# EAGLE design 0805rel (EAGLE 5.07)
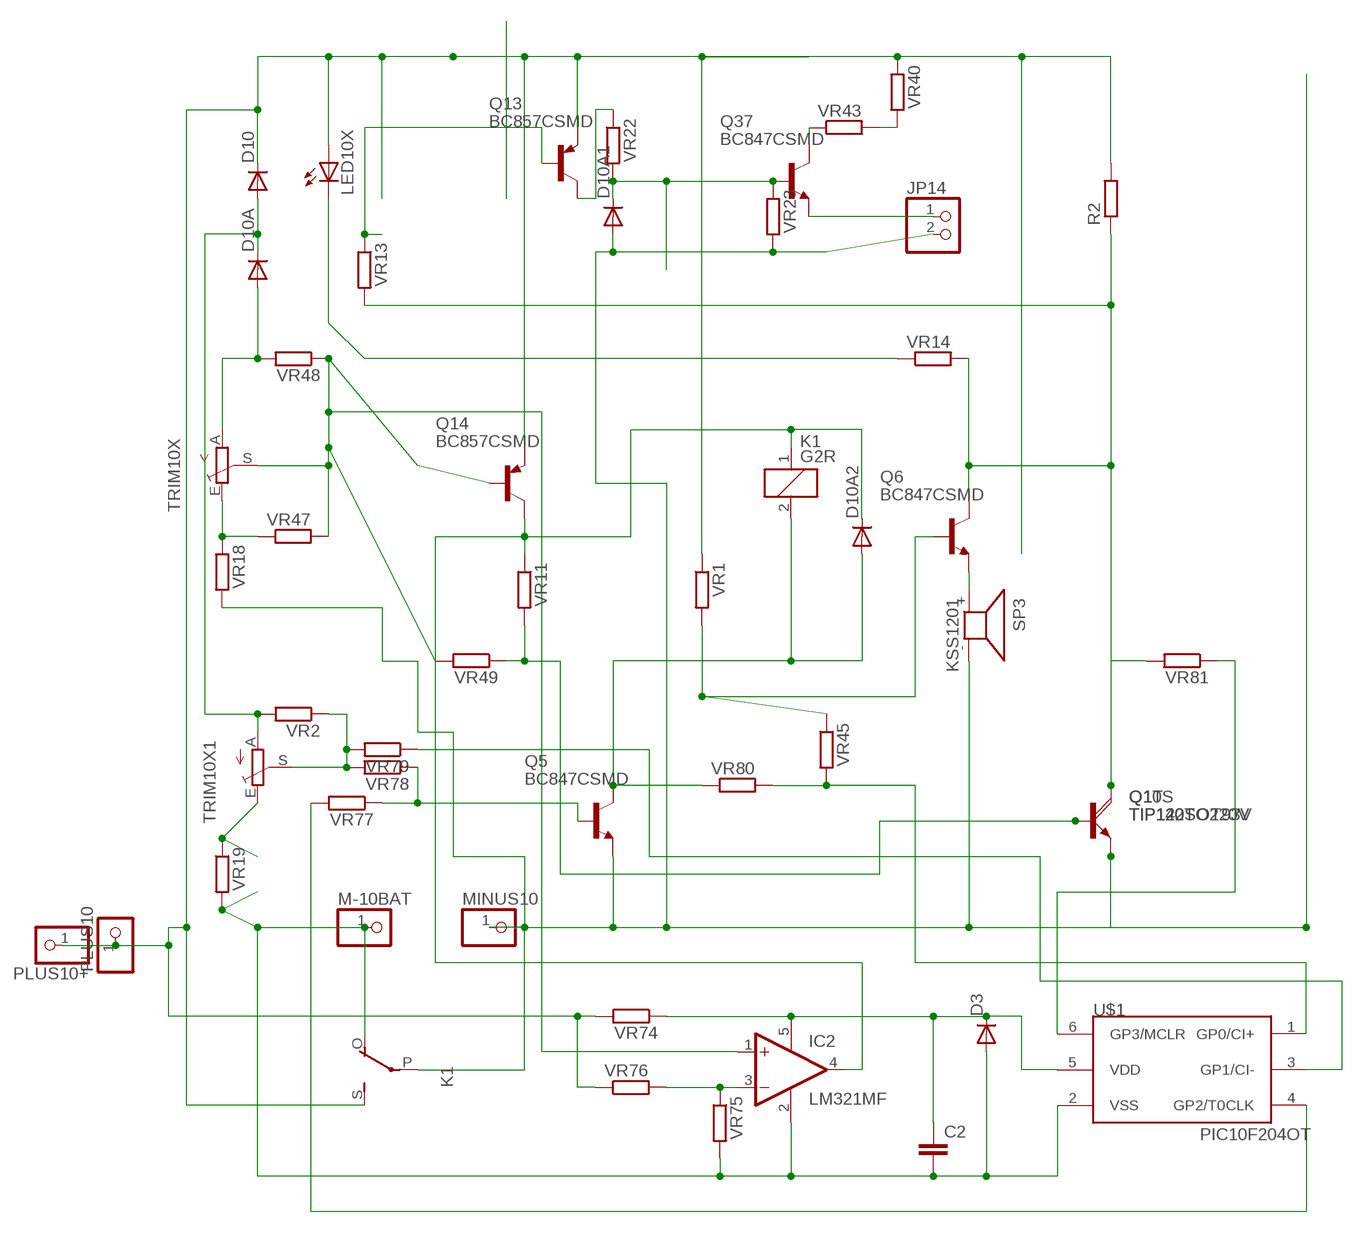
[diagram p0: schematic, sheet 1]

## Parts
C2  C-EUC0805  [C0805]
D3  DIODE-MINIMELF  [MINIMELF]
D10  DIODE-MINIMELF  [MINIMELF]
D10A  DIODE-MINIMELF  [MINIMELF]
D10A1  DIODE-MINIMELF  [MINIMELF]
D10A2  DIODE-MINIMELF  [MINIMELF]
IC2  LM321MF  [SOT23-5]
JP14  PINHD-1X2STR  [1X02]
K1  G2R  [G2R]
LED10X  LEDCHIPLED_1206  [CHIPLED_1206]
M-10BAT  PINHD-1X11X0.4  [1X01]
MINUS10  PINHD-1X14.5MM  [1X4MM5]
PLUS10  PINHD-1X14.5MM  [1X4MM5]
PLUS10+  PINHD-1X11X0.4  [1X01]
Q1  TIP142SOT93V  [SOT93V]
Q1T  TIP120TO220V  [TO220AV]
Q5  BC847CSMD  [SOT23]
Q6  BC847CSMD  [SOT23]
Q10S  TIP120  TIP120DPAK  [D-PAK_TO252AA]
Q13  BC857CSMD  [SOT23-BEC]
Q14  BC857CSMD  [SOT23-BEC]
Q37  BC847CSMD  [SOT23]
R2  R-EU_CERAM85  [CERAM85]
SP3  KSS1201  [KSS1201]
TRIM10X  TRIM_EU-S64W  [S64W]
TRIM10X1  TRIM_EU-S64W  [S64W]
U$1  PIC10F204OT  [SOT23-6]
VR1  R-EU_R0805  [R0805]
VR2  R-EU_R0805  [R0805]
VR11  R-EU_R0805  [R0805]
VR13  R-EU_R0805  [R0805]
VR14  R-EU_R0805  [R0805]
VR18  R-EU_R1206  [R1206]
VR19  R-EU_R1206  [R1206]
VR22  R-EU_R0805  [R0805]
VR23  R-EU_R0805  [R0805]
VR40  R-EU_R1206  [R1206]
VR43  R-EU_R1206  [R1206]
VR45  R-EU_R0805  [R0805]
VR47  R-EU_R0805  [R0805]
VR48  R-EU_R0805  [R0805]
VR49  R-EU_R0805  [R0805]
VR74  R-EU_R0805  [R0805]
VR75  R-EU_R0603  [R0603]
VR76  R-EU_R0805  [R0805]
VR77  R-EU_R0805  [R0805]
VR78  R-EU_R0805  [R0805]
VR79  R-EU_R0805  [R0805]
VR80  R-EU_R0805  [R0805]
VR81  R-EU_R0805  [R0805]

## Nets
B: IC2.1(+IN) Q14.B TRIM10X.S VR47.2 VR48.1 VR49.2
B2: U$1.4(GP2/T0CLK) VR77.2
E10: D10A1.A JP14.2 K1.P(2:P) MINUS10.1 Q1.E Q1T.E Q5.2(E) Q10S.3(E) SP3.- VR18.2 VR23.2
GP3: Q6.2(E) SP3.+
N$11: LED10X.C VR14.1
N$14: D10A.A TRIM10X.A VR48.2
N$15: D10A2.C IC2.4(OUT) K1.1 Q14.C VR11.1
N$17: D10.A D10A.C TRIM10X1.A VR2.2
N$22: TRIM10X1.S VR2.1 VR78.2 VR79.2
N$23: Q13.B VR13.1
N$24: TRIM10X1.E VR19.1
N$25: Q1.B Q1T.B Q10S.1(B) VR11.2 VR49.1
N$128: TRIM10X.E VR18.1 VR47.1
N$136: JP14.1 Q37.2(E)
N$138: U$1.1(GP0/CI+) VR45.2 VR80.2
N$146: Q6.1(B) VR1.2 VR45.1
N$149: IC2.3(-IN) VR75.1 VR76.2
N$159: Q13.C VR22.1
N$163: VR40.2 VR43.2
N$164: Q37.3(C) VR43.1
N$165: U$1.3(GP1/CI-) VR79.1
N$168: Q5.1(B) VR77.1 VR78.1
N$169: D10A2.A K1.2 Q5.3(C) VR80.1
N$170: U$1.6(GP3/MCLR) VR81.1
N$179: D10A1.C Q37.1(B) VR22.2 VR23.1
PLUS11: D10.C K1.S(2:S) LED10X.A PLUS10+.1 PLUS10.1 Q13.E Q14.E R2.2 VR1.1 VR40.1 VR74.2 VR76.1
Q10C: Q1.C Q1T.C Q6.3(C) Q10S.4(C) R2.1 VR13.2 VR14.2 VR81.2
V3: C2.1 D3.C IC2.5(V+) U$1.5(VDD) VR74.1
VSS: C2.2 D3.A IC2.2(V-) K1.O(2:O) M-10BAT.1 U$1.2(VSS) VR19.2 VR75.2

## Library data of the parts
C2 = rcl:C-EU: CAPACITOR, European symbol
D3 D10 D10A D10A1 D10A2 = diode:DIODE-: DIODE
IC2 = linear:LM321?*: Low Power Single Op Amp Source: http://cache.national.com/ds/LM/LM321.pdf
JP14 = pinhead:PINHD-1X2: PIN HEADER
K1 = relay:G2R: RELAY 1 x switch, Omron
LED10X = led:LED: LED
M-10BAT MINUS10 PLUS10 PLUS10+ = pinhead:PINHD-1X1: PIN HEADER
Q1 = transistor-power:TIP142: NPN DARLINGTON TRANSISTOR
Q1T Q10S = transistor-power:TIP120: NPN DARLINGTON TRANSISTOR
Q5 Q6 Q37 = transistor-npn:BC847*: NPN Transistor
Q13 Q14 = transistor-pnp:BC857*: PNP Transistror
R2 = rcl:R-EU_: RESISTOR, European symbol
SP3 = buzzer:KSS1201: SPEAKER
TRIM10X TRIM10X1 = pot:TRIM_EU-: POTENTIOMETER
U$1 = microchip-3:PIC10F2*: uPC nW 0,25/0,5k Program Flash memory Comparator
VR1 VR2 VR11 VR13 VR14 VR18 VR19 VR22 VR23 VR40 VR43 VR45 VR47-VR49 VR74-VR81 = rcl-2:R-EU_: RESISTOR, European symbol

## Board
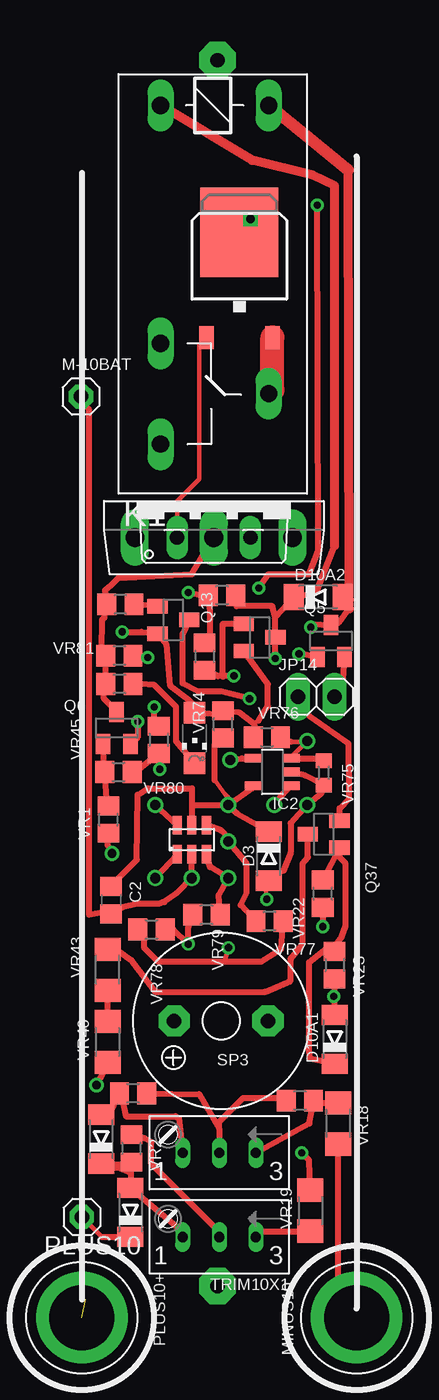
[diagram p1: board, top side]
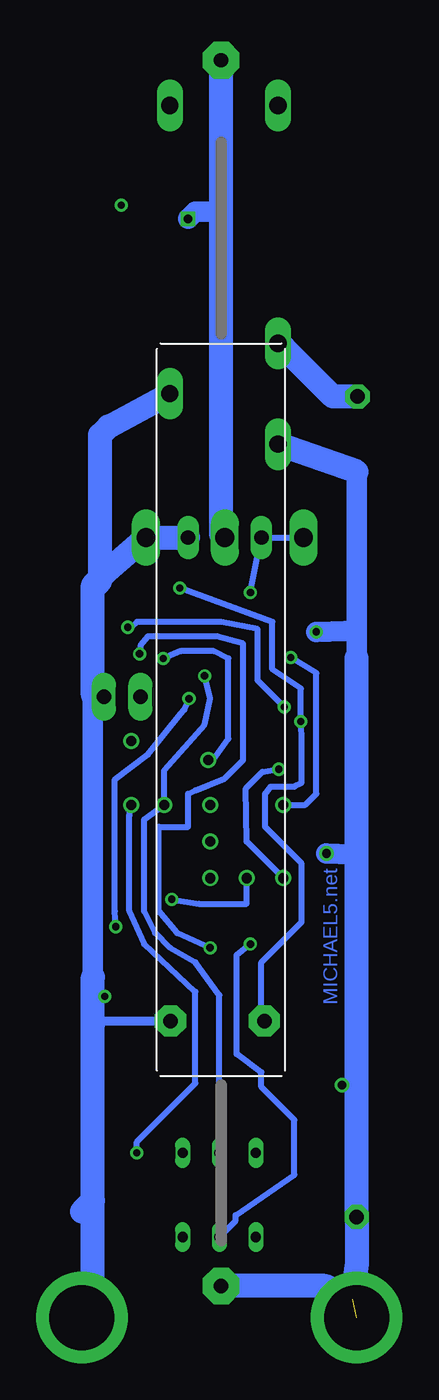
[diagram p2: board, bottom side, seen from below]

No outline drawn. Coordinates in mm, seen from the top.
Copper layers (1*16): Top 0.035mm / dielectric 1.5mm / Bottom 0.035mm
Design rules "default *": minimum track width 8mil, minimum drill 24mil, track to track 8mil, track to pad 8mil, pad to pad 8mil, via to via 8mil, smd to smd 8mil, copper to edge 40mil, drill to drill 8mil, minimum pad ring 1mil, minimum via ring 8mil, stop-mask expansion 4mil, vias tented up to drill 0mil, thermal gap 10mil

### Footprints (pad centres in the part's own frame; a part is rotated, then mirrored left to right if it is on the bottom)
C0805 = smd 1.3 x 1.5: 1 -0.95,0; 2 0.95,0
MINIMELF = smd 1.4 x 1.8: A 1.7,0; C -1.7,0
SOT23-5 = smd 0.6 x 1.2: 1 -0.95,-1.306; 2 0,-1.306; 3 0.95,-1.306; 4 0.95,1.306; 5 -0.95,1.306
1X02 = drill 1.016 pad 1.676 long: 1 -1.27,0; 2 1.27,0
G2R = drill 1.2 pad 1.778 long: 1 -2.54,-3.683; 2 -2.54,3.81; O 13.97,-3.683; P 17.45,3.81; S 20.955,-3.683
CHIPLED_1206 = smd 1.5 x 1.5: A 0,-1.75; C 0,1.75
1X01 = drill 1 pad 1.676 octagon: 1 0,0
1X4MM5 = drill 4.5 pad 6.35 round: 1 0,0
SOT93V = drill 1.3 pad 1.676 long: B -5.461,-2.54; C 0,-2.54; E 5.461,-2.54
TO220AV = drill 1 pad 1.27 long: B -2.54,-2.54; C 0,-2.54; E 2.54,-2.54
SOT23 = smd 1 x 1.4: 1 -0.95,-1.1; 2 0.95,-1.1; 3 0,1.1
D-PAK_TO252AA = smd 1 x 1.6: 1 -2.28,-4.8; 3 2.28,-4.8 | smd 5.4 x 6.2: 4 0,2.5
SOT23-BEC = smd 1 x 1.4: B -0.95,-1.1; C 0,1.1; E 0.95,-1.1
CERAM85 = drill 1 pad 2.54 octagon: 1 -42.5,0; 2 42.5,0
KSS1201 = drill 1 pad 2.159 octagon: + 3.251,0; - -3.251,0
S64W = drill 0.7 long: A 2.54,1.27; E -2.54,1.27; S 0,1.27
SOT23-6 = smd 0.635 x 1.27: 1 -1.016,-1.016; 2 0,-1.016; 3 1.016,-1.016; 4 1.016,1.016; 5 0,1.016; 6 -1.016,1.016
R0805 = smd 1.3 x 1.5: 1 -0.95,0; 2 0.95,0
R1206 = smd 1.6 x 1.803: 1 -1.422,0; 2 1.422,0
R0603 = smd 1 x 1.1: 1 -0.85,0; 2 0.85,0

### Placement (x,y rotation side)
C2  73.15,37.85 270 top
D3  84.07,40.89 270 top
D10  74.49,16.19 90 top
D10A  72.45,21.27 90 top
D10A1  88.65,28.19 90 top
D10A2  87.5,58.86 0 top
IC2  84.33,46.74 90 top
JP14  87.38,51.94 0 top
K1  80.26,90.42 270 top
LED10X  78.93,49.09 180 top
M-10BAT  71.06,72.77 0 top
MINUS10  90.17,8.89 0 top
PLUS10  71.12,8.89 0 top
PLUS10+  71.12,15.88 0 top
Q1  80.26,65.53 0 top
Q1T  80.26,65.53 0 top
Q5  88.39,55.82 0 top
Q6  73.53,49.78 0 top
Q10S  82.04,81.66 0 top
Q13  77.47,57.28 270 top
Q14  83.44,56.07 270 top
Q37  87.88,42.42 90 top
R2  80.52,53.59 270 bottom
SP3  80.77,29.46 180 top
TRIM10X  80.64,21.59 180 top
TRIM10X1  80.64,15.75 180 top
U$1  78.74,42.04 0 top
VR1  72.96,43.43 90 top
VR2  74.55,20.64 270 top
VR11  80.84,58.99 180 top
VR13  73.79,58.36 180 top
VR14  73.72,52.83 180 top
VR18  88.9,22.35 270 top
VR19  86.97,16.32 90 top
VR22  87.82,38.29 90 top
VR23  88.65,33.34 270 top
VR40  72.9,28 90 top
VR43  72.9,33.02 270 top
VR45  73.66,46.74 0 top
VR47  86.23,23.94 180 top
VR48  74.68,24.45 180 top
VR49  79.63,54.74 270 top
VR74  80.9,50.04 90 top
VR75  87.88,46.67 270 top
VR76  83.95,49.15 0 top
VR77  84.14,36.39 180 top
VR78  75.95,35.81 0 top
VR79  79.76,36.83 180 top
VR80  76.45,48.96 270 top
VR81  73.72,54.8 180 top

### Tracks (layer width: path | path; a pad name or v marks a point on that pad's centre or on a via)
B  (via drill 0.5, 0.7)
  Top 0.406: 80.64,21.97 80.64,22.48 82.3,24.13 85.19,24.13 VR47.2 | 80.64,21.97 TRIM10X.S | 80.64,21.97 79.25,24.38 VR48.1 | v81.66,53.4 81.47,53.38 | v84.45,44.45 85.09,45.24 IC2.1 | VR49.2 80.54,53.38 v81.66,53.4 | Q14.B 82.42,57.02 80.9,57.02 80.9,53.34 v81.66,53.4
  Bottom 0.406: TRIM10X.S 80.64,31.24 82.3,33.53 84.07,34.54 85.09,35.56 85.85,37.08 85.85,43.43 v84.45,44.45 84.45,46.86 81.66,50.04 81.28,51.82 v81.66,53.4
B2  (via drill 0.7)
  Top 0.406: VR77.2 82.13,37.5 82.55,38.35 82.55,40.39 v81.28,41.91 81.28,42.16 80.77,42.67 U$1.4
  Bottom 0.406: v81.28,41.91 81.28,42.16
E10  (via drill 0.5)
  Top 0.406: VR18.2 88.9,10.92 MINUS10.1 | VR23.2 88.71,32.07 v88.58,31.18 D10A1.A | Q5.2 89.22,52.64 JP14.2
  Top 1.676: K1.P 84.32,73.22 Q10S.3
  Bottom 0.406: MINUS10.1 89.41,9.65 | v88.58,31.18 89.15,32.26 89.41,32.51 | 89.41,52.07 JP14.2
  Bottom 0.61: SP3.- 89.15,29.46 89.41,29.21
  Bottom 1.422: 89.41,32.51 89.41,52.07
  Bottom 1.676: 89.41,17.02 90.17,16.26 | 89.41,17.02 89.41,29.21 89.41,32.51 | 89.41,52.07 89.41,59.44 | 89.41,59.44 89.41,59.69 88.65,60.45 Q1.E Q1T.E | K1.P 88.32,70.69 88.9,70.1 88.9,59.94 89.41,59.44 | 89.41,9.65 89.41,17.02
GP3  (via drill 0.5)
  Top 0.406: v74.99,50.23 74.99,49.13 Q6.2 | v83.38,59.5 84.07,60.45 86.87,60.45 87.57,62.23 87.5,62.17 v87.44,86.04
  Bottom 0.406: SP3.+ 77.72,29.67 77.72,33.53 74.93,36.32 74.93,40.39 77.47,42.93 77.47,45.21 77.09,45.72 75.44,45.72 74.93,45.97 74.93,49.28 v74.99,50.23 74.99,52.51 76.96,53.85 76.96,57.15 v83.38,59.5
N$11
  Top 0.406: VR14.1 75.18,52.83 76.14,52.77 77.66,51.24 77.66,48.86 LED10X.C
N$14
  Top 0.406: D10A.A 73.15,23.23 VR48.2 73.91,24.04 74.17,22.86 77.6,22.86 77.85,22.73 TRIM10X.A
N$15  (via drill 0.5, 0.7)
  Top 0.406: IC2.4 82.23,47.69 v81.41,47.56 | VR11.1 81.83,58.23 84.33,58.23 84.54,57.49 | v84.52,54.61 Q14.C 84.54,57.49 | 88.65,62.42 87.38,59.18 D10A2.C 84.54,57.49
  Top 0.61: 88.65,62.42 88.65,87.38 87.12,88.14 82.93,89.15 K1.1
  Bottom 0.406: v81.41,47.56 80.9,47.82 80.01,49.02 80.01,54.61 81.03,55.12 83.31,55.12 v84.52,54.61
N$17
  Top 0.406: VR2.2 73.94,19.53 D10A.C 72.64,19.25 73.66,19.3 74.5,18.97 D10.A 78.11,14.85 TRIM10X1.A
N$22  (via drill 0.5)
  Top 0.406: TRIM10X1.S 80.64,14.86 75.95,19.56 75.95,21.08 75.46,21.34 VR2.1 | VR79.2 78.49,35.9 v78.49,34.8 77.47,35.81 VR78.2
  Bottom 0.406: v78.49,34.8 79.44,34.04 79.44,27.18 77.72,25.91 77.72,24.89 75.44,22.61 75.44,18.8 79.5,16 79.5,15.62 TRIM10X1.S
N$23
  Top 0.406: Q13.B 74.65,58.35 VR13.1
N$24
  Top 0.406: VR19.1 83.19,14.9 TRIM10X1.E
N$25  (via drill 0.5)
  Top 0.305: Q10S.1 79.25,76.35 79.25,67.06 77.72,65.53 Q1T.B
  Top 0.406: VR49.1 80.01,55.97 80.01,57.91 VR11.2 79.5,58.93 v78.49,59.18
  Bottom 0.406: v78.49,59.18 Q1T.B Q1.B
N$128
  Top 0.406: TRIM10X.E 86.89,22.35 VR47.1 87.25,23.77 VR18.1
N$136
  Top 0.406: Q37.2 88.98,44.22 89.66,44.9 89.62,48.68 86.61,50.8 86.61,51.56 JP14.1
N$138  (via drill 0.5, 0.7)
  Top 0.406: v76.2,39.37 U$1.1 | VR45.2 74.76,46.67 VR80.2 76.54,47.03 v76.52,46.93
  Bottom 0.406: v76.52,46.93 77.66,46.74 78.8,45.59 78.74,41.91 v76.2,39.37
N$146
  Top 0.406: VR1.2 72.96,44.77 72.83,44.9 VR45.1 Q6.1
N$149  (via drill 0.7)
  Top 0.305: IC2.3 85.63,47.79 v86.74,48.9 86.56,48.82 85.63,48.82
  Top 0.406: IC2.3 87.73,47.69 VR75.1 | 85.63,48.82 VR76.2
N$159  (via drill 0.5)
  Top 0.406: v82.74,51.82 80.77,52.32 79.18,52.32 78.11,52.88 78.11,56.3 Q13.C | VR22.1 v87.82,36.01
  Bottom 0.406: v82.74,51.82 83.06,51.05 83.31,50.8 85.6,47.94 87.88,46.23 87.88,37.08 v87.82,36.01
N$163
  Top 0.406: VR40.2 VR43.2
N$164
  Top 0.406: VR43.1 73.51,34.44 74.56,33.68 76.2,31.5 83.82,31.5 85.6,32.26 85.6,33.78 86.42,34.8 86.42,40.39 86.78,40.81 Q37.3
N$165  (via drill 0.7)
  Top 0.406: U$1.3 80.01,40.13 v81.28,39.37 80.61,38.19 VR79.1
N$168  (via drill 0.5)
  Top 0.305: 81.03,33.59 v81.28,34.54
  Top 0.406: VR77.1 84.94,34.46 83.57,33.59 81.03,33.59 76.39,33.59 75.44,34.54 75.44,35.73 VR78.1 | Q5.1 86.57,54.91 v86.17,54.93
  Bottom 0.406: v81.28,34.54 83.57,35.56 84.84,37.08 84.84,42.93 82.8,42.93 82.8,45.21 82.3,45.47 80.26,46.29 78.99,47.56 78.99,55.63 80.77,56.13 85.6,56.13 86.11,55.5 v86.17,54.93
N$169  (via drill 0.5)
  Top 0.406: v87,56.77 87.04,56.98 Q5.3 88.96,57.11 89.66,58.06 | VR80.1 76.33,49.66 76.14,50.1 v76.14,51.24 | D10A2.A 89.66,58.8 89.66,58.67
  Top 0.61: 89.66,58.06 89.66,58.67 89.6,88.46
  Top 0.813: K1.2 86.87,90.68 89.6,88.46
  Bottom 0.406: v87,56.77 86.74,56.77 86.36,57.15 80.52,57.15 77.98,56.64 77.98,53.09 v76.14,51.24
N$170  (via drill 0.5, 0.7)
  Top 0.406: U$1.6 v76.2,44.45 | v75.69,54.67 VR81.1
  Bottom 0.406: v76.2,44.45 74.68,44.45 73.91,45.21 73.91,53.59 v75.69,54.67
N$179
  Top 0.406: D10A1.C 86.95,26.85 86.87,27.43 86.87,33.53 88.14,34.54 88.58,34.54 | 88.58,34.54 VR23.1 | Q37.1 88.46,41.47 | 88.58,34.54 89.15,35.31 89.41,36.07 89.41,40.39 88.98,40.81 Q37.1 | Q37.1 VR22.2
PLUS11  (via drill 0.5, 0.6)  (1 unrouted)
  Top 0.305: 83.38,50.29 83.12,50.17 83.04,50.09 | PLUS10+.1 72.5,14.49
  Top 0.406: VR1.1 72.9,41.66 v73.22,41.08 | VR40.1 72.39,25.5 v72.14,25.02 | 83.38,50.29 84.01,51.31 84.01,52.83 Q14.E | VR76.1 83.1,49.97 83.04,50.09 81.98,50.89 VR74.2 81.14,50.77 LED10X.A 78.8,51.44 78.49,51.75 77.22,52.73 76.96,55.61 Q13.E 75.25,56.45 v73.91,56.45 | 72.5,14.49 D10.C
  Bottom 0.305: 71.12,17.14 71.12,23.88 v72.14,25.02 | PLUS10+.1 71.12,11.18 72.39,9.91
  Bottom 0.406: 71.5,41.02 71.5,37.85 71.12,27.43 70.87,26.42 v72.14,25.02 | 71.12,54.61 71.89,56.52
  Bottom 1.422: 71.5,41.02 v73.22,41.08 | 71.12,54.61 71.12,67.56 | 71.89,56.52 v73.91,56.45
  Bottom 1.676: 71.12,67.56 K1.S | 72.39,9.91 71.37,10.16 | 71.37,10.16 71.12,12.45 PLUS10+.1 71.12,17.14 71.12,54.61 | R2.2 73.32,11.09 71.37,10.16
Q10C  (via drill 0.6)
  Top 0.406: Q6.3 73.53,50.93 72.64,51.82 72.64,52.7 VR14.2 VR81.2 72.49,55.26 72.52,57.28 72.68,57.44 VR13.2 72.73,59.35 73.15,59.69 73.66,60.2 78.74,60.45 Q1.C | Q10S.4 82.8,84.92 v82.8,85.09
  Bottom 1.422: v82.8,85.09 82.3,85.6 80.52,85.6
  Bottom 1.676: R2.1 80.52,85.6 80.52,63.25 Q1.C
V3  (via drill 0.7)
  Top 0.305: 80.33,46.16 81.03,45.21 81.28,44.96 v81.28,44.45
  Top 0.406: 78.74,44.45 U$1.5 | 78.74,44.45 v81.28,44.45 | D3.C 81.87,43.86 v81.28,44.45 | C2.1 73.15,38.86 74.93,40.64 74.99,45.15 75.69,45.59 78.74,45.59 78.74,44.45 | IC2.5 83.02,45.68 v81.28,44.45 | 80.33,46.16 80.33,48.62 VR74.1
VSS  (via drill 0.5, 0.7)
  Top 0.305: v83.95,37.91 83.82,38.94 D3.A 85.09,39.88
  Top 0.406: U$1.2 v78.74,39.37 77.72,38.35 76.83,37.72 76.45,37.59 74.93,37.59 73.91,37.34 73.15,37.08 | M-10BAT.1 71.06,72.45 71.63,71.88 71.63,36.83 73.15,37.08 | VR19.2 86.87,19.81 v86.36,20.32 | 73.15,37.08 C2.2 | IC2.2 86.61,46.48 VR75.2 87.73,45.25 v86.74,44.45 85.6,43.18 85.6,41.15 85.09,39.88 | D3.A 83.82,39.7
  Bottom 0.406: v86.36,20.32 86.36,21.08 82.3,25.15 82.3,31.5 85.85,34.8 86.87,37.08 86.87,43.69 v86.74,44.45 | v78.74,39.37 78.74,37.59 82.04,37.59 v83.95,37.91
  Bottom 1.676: M-10BAT.1 72.77,72.77 76.2,76.2 76.33,76.2 K1.O

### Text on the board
Bottom: MICHAEL5.net
tStop: MICHAEL5.net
